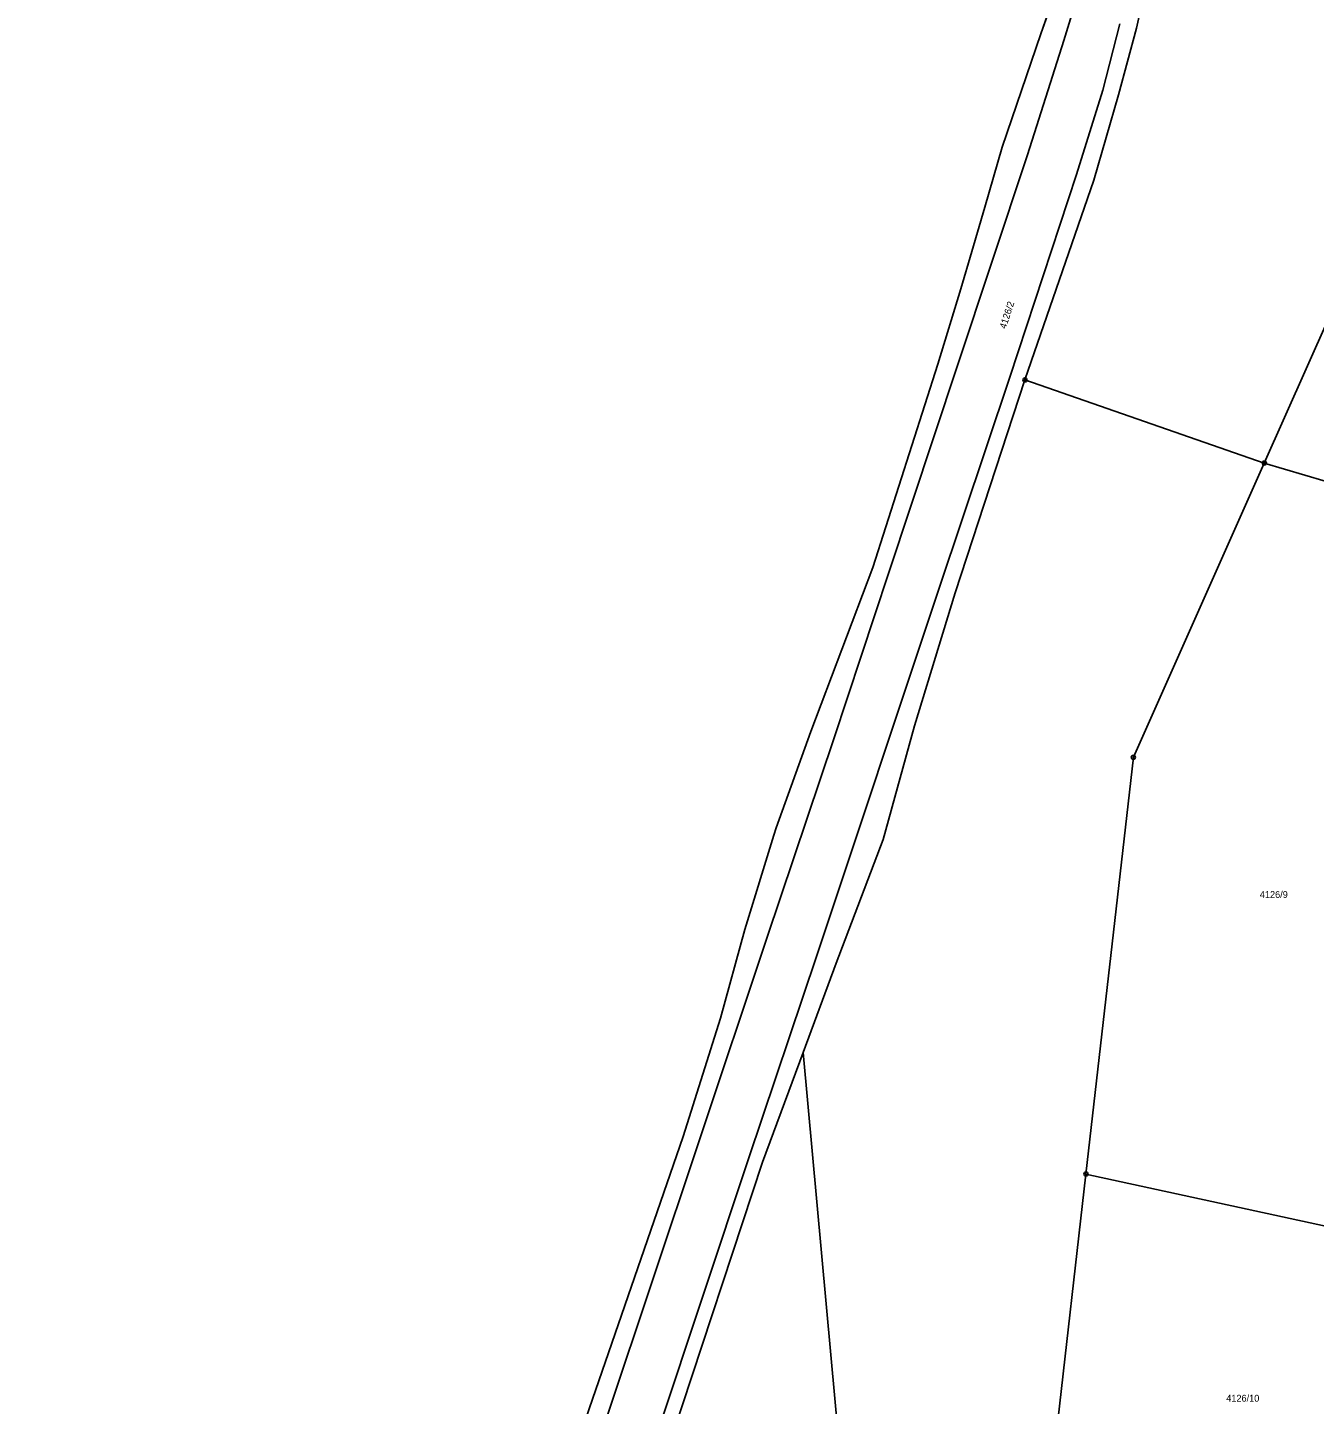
# Model space of a CAD drawing. Extents: x -733394 to -722299, y -1082822 to -1075049.
# Drawn here: x -729787.4 to -729467.8, y -1081269.6 to -1080927.6 of the extents above; entities that cross this region are included whole.
import ezdxf

# ---------------------------------------------------------------- set-up
doc = ezdxf.new("R2010")
doc.units = 0
for name, color, linetype in [('Hranice parcel', 7, 'Continuous'), ('Parcelní čísla', 7, 'Continuous'), ('Polygon ku', 7, 'Continuous'), ('Vnitřní kresba', 7, 'Continuous'), ('Značky bodu BP', 7, 'Continuous')]:
    doc.layers.add(name, color=color, linetype=linetype)

msp = doc.modelspace()

# ---------------------------------------------------------------- linework, layer by layer
at = {"layer": 'Hranice parcel'}
for p, q in [((-729528.58, -1080908.9), (-729535.77, -1080929.23)), ((-729535.77, -1080929.23), (-729545.34, -1080957.35)), ((-729545.34, -1080957.35), (-729549.69, -1080972.24)), ((-729549.69, -1080972.24), (-729552.92, -1080983.29)), ((-729555.61, -1080992.51), (-729552.92, -1080983.29)), ((-729561.35, -1081011.25), (-729555.61, -1080992.51)), ((-729539.7, -1081015.17), (-729480.25, -1081035.81)), ((-729480.25, -1081035.81), (-729430.43, -1081050.71)), ((-729609.3, -1081151.64), (-729602.03, -1081128.2)), ((-729615.27, -1081173.67), (-729609.3, -1081151.64)), ((-729524.54, -1081212.42), (-729534.57, -1081300.68)), ((-729524.54, -1081212.42), (-729431.71, -1081232.65))]:
    msp.add_line(p, q, dxfattribs=at)
for points in [[(-729539.7, -1081015.17), (-729522.56, -1080965.51), (-729516.43, -1080944.36), (-729511.98, -1080927.79), (-729508.56, -1080912.15), (-729496.2, -1080868.75), (-729487.89, -1080830.6), (-729481.78, -1080799.44), (-729479.87, -1080787.09), (-729479.68, -1080785.67)], [(-729480.25, -1081035.81), (-729437.54, -1080939.88), (-729251.05, -1080976.13)], [(-729602.03, -1081128.2), (-729601.47, -1081126.4), (-729592.89, -1081102.5), (-729577.49, -1081061.78), (-729561.35, -1081011.25)], [(-729594.79, -1081182.2), (-729586.58, -1081160.07), (-729574.89, -1081129.3), (-729567.15, -1081101.06), (-729557.01, -1081068.02), (-729539.7, -1081015.17)], [(-729480.25, -1081035.81), (-729512.78, -1081108.9), (-729524.54, -1081212.42)], [(-729647.95, -1081270.73), (-729624.61, -1081203.1), (-729615.27, -1081173.67)], [(-729787.39, -1081845.53), (-729786.43, -1081841.78), (-729778.92, -1081810.98), (-729775.89, -1081795.07), (-729773.13, -1081770.84), (-729771.8, -1081755.39), (-729765.07, -1081687.62), (-729756.33, -1081654.49), (-729753.68, -1081645.05), (-729739.14, -1081619.84), (-729725.58, -1081596.33), (-729716.87, -1081573.65), (-729709.3, -1081548.65), (-729696.27, -1081504.71), (-729682.23, -1081454.93), (-729678.15, -1081431.64), (-729666.95, -1081404.54), (-729659.65, -1081384.76), (-729652.75, -1081358.56), (-729627.33, -1081277.56), (-729604.91, -1081209.48), (-729594.79, -1081182.2)], [(-729594.79, -1081182.2), (-729585.66, -1081281.78), (-729576.53, -1081381.36), (-729567.4, -1081480.95), (-729474.06, -1081539.95)]]:
    msp.add_lwpolyline(points, dxfattribs=at)
at = {"layer": 'Polygon ku'}
for points in [[(-729528.58, -1080908.9), (-729535.77, -1080929.23), (-729545.34, -1080957.35), (-729549.69, -1080972.24), (-729552.92, -1080983.29), (-729555.61, -1080992.51), (-729561.35, -1081011.25), (-729577.49, -1081061.78), (-729592.89, -1081102.5), (-729601.47, -1081126.4), (-729602.03, -1081128.2)], [(-729602.03, -1081128.2), (-729609.3, -1081151.64), (-729615.27, -1081173.67), (-729624.61, -1081203.1), (-729647.95, -1081270.73), (-729655.04, -1081292.18), (-729666.39, -1081326.49), (-729675.61, -1081345.3), (-729677.28, -1081349.23), (-729678.35, -1081351.75), (-729692.18, -1081384.43), (-729698.38, -1081402.91), (-729719.61, -1081455.1), (-729723.5, -1081464.86), (-729727.7, -1081475.91), (-729740.08, -1081508.5), (-729759.96, -1081560.33), (-729765.79, -1081578.43)]]:
    msp.add_lwpolyline(points, dxfattribs=at)
at = {"layer": 'Vnitřní kresba'}
for p, q in [((-729530.03, -1080930.88), (-729523.75, -1080909.85)), ((-729516.13, -1080926.72), (-729520.38, -1080943.19)), ((-729539.09, -1080959.25), (-729530.03, -1080930.88)), ((-729520.38, -1080943.19), (-729526.89, -1080964.17)), ((-729539.09, -1080959.25), (-729556.54, -1081011.8)), ((-729526.89, -1080964.17), (-729543.49, -1081014.44)), ((-729556.54, -1081011.8), (-729573.61, -1081063.23)), ((-729543.49, -1081014.44), (-729560.99, -1081066.85)), ((-729573.61, -1081063.23), (-729587.19, -1081104.32)), ((-729591.49, -1081158.37), (-729560.99, -1081066.85)), ((-729603.7, -1081153.61), (-729587.19, -1081104.32)), ((-729603.7, -1081153.61), (-729620.7, -1081204.41)), ((-729608.26, -1081208.41), (-729591.49, -1081158.37)), ((-729620.7, -1081204.41), (-729643.4, -1081272.33)), ((-729630.81, -1081276.09), (-729608.26, -1081208.41))]:
    msp.add_line(p, q, dxfattribs=at)
at = {"layer": 'Značky bodu BP'}
for centre, radius in [((-729539.7, -1081015.17), 0.5), ((-729539.7, -1081015.17), 0.0303), ((-729480.25, -1081035.81), 0.5), ((-729480.25, -1081035.81), 0.0303), ((-729512.78, -1081108.9), 0.5), ((-729512.78, -1081108.9), 0.0303), ((-729524.54, -1081212.42), 0.5), ((-729524.54, -1081212.42), 0.0303)]:
    msp.add_circle(centre, radius, dxfattribs=at)

# ---------------------------------------------------------------- texts
at = {"layer": 'Parcelní čísla'}
msp.add_text('4126/2', height=1.7, rotation=72, dxfattribs=at).set_placement((-729544.46, -1081002.6))
for s, p in [('4126/9', (-729481.37, -1081143.83)), ('4126/10', (-729489.71, -1081268.95))]:
    msp.add_text(s, height=1.7, dxfattribs=at).set_placement(p)

doc.saveas('drawing.dxf')
